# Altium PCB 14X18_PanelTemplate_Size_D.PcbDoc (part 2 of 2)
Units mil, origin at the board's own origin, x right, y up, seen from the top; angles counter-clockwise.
Board outline 18000 x 14000 mil, 2 copper layers (Top Layer, Bottom Layer); 52 components, 1 nets, 312 pads, 0 vias.
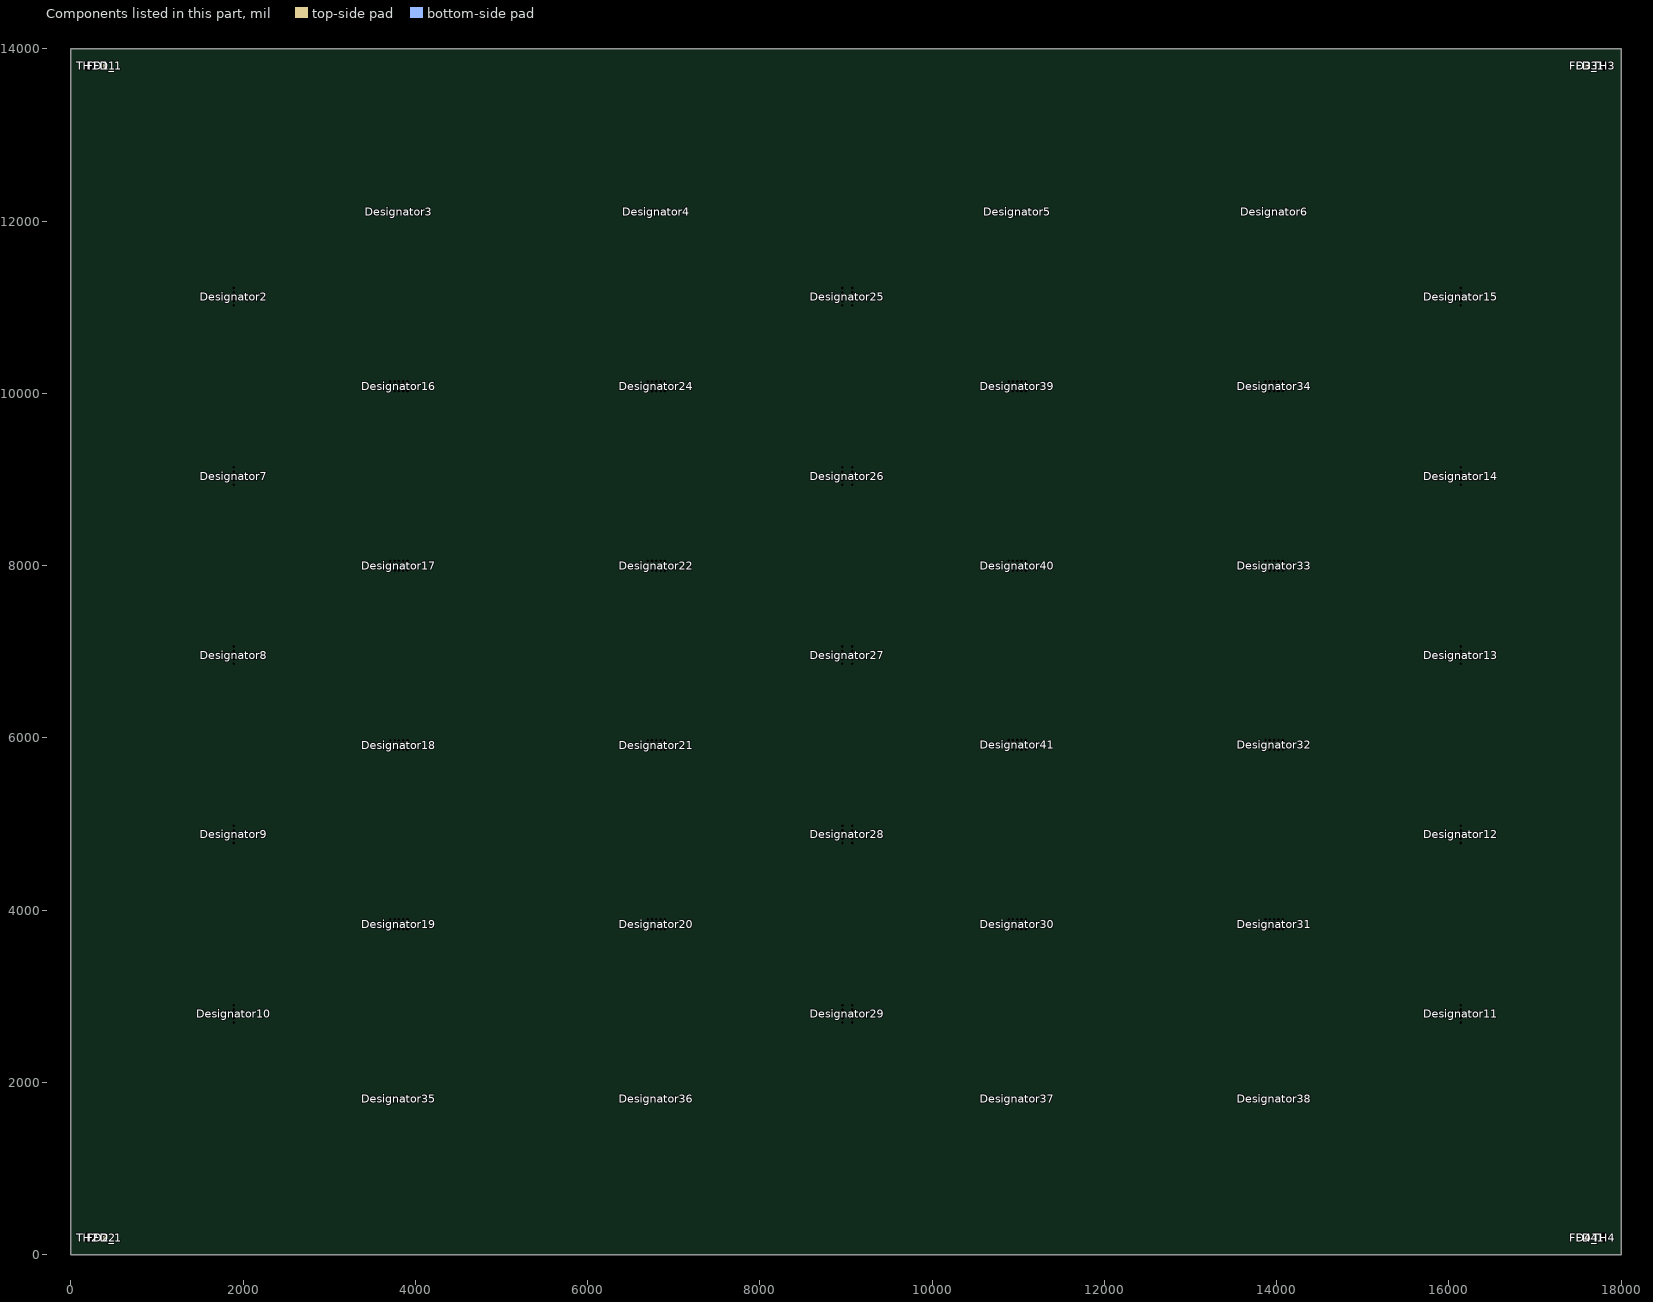
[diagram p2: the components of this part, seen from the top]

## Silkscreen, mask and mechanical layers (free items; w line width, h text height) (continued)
32_PANEL_CONTINUATION_BLOCK_MIRRORED:
  lines w1: -3000,-2999 31000,-2999 31000,19001 -3000,19001 -3000,-2999 ; -2700,-2699 -2700,18701 30700,18701 30700,-2699 -2700,-2699
  lines w5: -2849,2761 -2700,2761 ; -2700,-2550 405,-2550 ; -2700,-2235 405,-2235 405,-2550 ; -2700,-1500 -2700,-2700 1800,-2700 ; -2700,2651 -2849,2651 -2849,3761 -2700,3761 ; -2698,18046 1095,18046 1095,18696 ; -2698,18176 1095,18176 ; -2698,18306 1095,18306 ; -2698,18436 1095,18436 ; -2698,18566 1095,18566 ; -2400,-2550 -2400,-2235 ; -2105,18046 -2105,18566 ; -1940,-2700.1 -1940,-2550.1 ; -1505,18046 -1505,18566 ; -900,-2550 -900,-2235 ; -400,18701 -400,18850 710,18850 710,18701 ; -290,18701 -290,18850 ; -200,-2700 -200,-2550 ; 100,-2550 100,-2235 ; 405,-2700 405,-2550 ; 495,18046 495,18566 ; 795,18046 795,18566 ; 27823,-2699 27823,-2503 ; 27823,-2699 30700,-2699 ; 27823,-2699 30700,-2699 ; 27823,-2699 27823,-2503 ; 27823,-2699 30700,-2699 ; 27823,-2699 27823,-2503 ; 27823,-2503 30700,-2503 ; 27823,-2503 30700,-2503 ; 27823,-2503 30700,-2503 ; 30700,-2699 30700,-2503 ; 30700,-2699 30700,-2503 ; 30700,-2699 30700,-2503 ; 28640,18371 28640,18701 30700,18701 30700,18371 28640,18371
  lines w10: -3000,2651 -2700,2651 ; -3000,8001 -2700,8001 ; -3000,13351 -2700,13351 ; 5650,-2999 5650,-2699 ; 5650,18701 5650,19001 ; 14000,-2999 14000,-2699 ; 14000,18701 14000,19001 ; 22350,-2999 22350,-2699 ; 22350,18701 22350,19001 ; 30700,2651 31000,2651 ; 30700,8001 31000,8001 ; 30700,13351 31000,13351
  text "REV:" at -315.09,18816 h30
  text "DWG. NO." at 694.91,18816 h30
  text "4" at 1400,18776 h250
  text "3" at 9750,18776 h250
  text "2" at 18100,18776 h250
  text "1" at 26475,18776 h250
  text ".PCB_REV" at -330,18726 h50
  text ".PCB_DWG_NO" at 480,18726 h50
  text "R" at 28804.21,18628.61 h76
  text "O" at 28859.22,18628.61 h76
  text "N" at 28927.57,18628.61 h76
  text "I" at 28947.57,18628.61 h76
  text "E" at 28994.25,18628.61 h76
  text "R" at 29042.6,18628.61 h76
  text "E" at 29089.28,18628.61 h76
  text "H" at 29139.29,18628.61 h76
  text "D" at 29207.64,18628.61 h76
  text "E" at 29254.32,18628.61 h76
  text "S" at 29300.99,18628.61 h76
  text "O" at 29356.01,18628.61 h76
  text "L" at 29394.35,18628.61 h76
  text "C" at 29444.36,18628.61 h76
  text "S" at 29491.04,18628.61 h76
  text "I" at 29509.38,18628.61 h76
  text "D" at 29559.39,18628.61 h76
  text "A" at 29626.07,18628.61 h76
  text "T" at 29667.75,18628.61 h76
  text "A" at 29714.43,18628.61 h76
  text "D" at 29764.44,18628.61 h76
  text "E" at 29829.46,18628.61 h76
  text "H" at 29879.47,18628.61 h76
  text "T" at 29922.81,18628.61 h76
  text "D" at 29991.16,18628.61 h76
  text "N" at 30041.18,18628.61 h76
  text "A" at 30087.85,18628.61 h76
  text "T" at 30151.2,18628.61 h76
  text "N" at 30199.55,18628.61 h76
  text "E" at 30246.23,18628.61 h76
  text "M" at 30304.57,18628.61 h76
  text "U" at 30354.59,18628.61 h76
  text "C" at 30404.6,18628.61 h76
  text "O" at 30459.61,18628.61 h76
  text "D" at 30509.62,18628.61 h76
  text "S" at 30574.64,18628.61 h76
  text "I" at 30594.65,18628.61 h76
  text "H" at 30644.66,18628.61 h76
  text "T" at 30688,18628.61 h76
  text "REVISIONS" at -540,18596 h60
  text "Y" at 28700.15,18548.59 h76
  text "A" at 28745.16,18548.59 h76
  text "M" at 28803.5,18548.59 h76
  text "D" at 28873.52,18548.59 h76
  text "N" at 28923.53,18548.59 h76
  text "A" at 28970.21,18548.59 h76
  text "D" at 29038.56,18548.59 h76
  text "E" at 29085.24,18548.59 h76
  text "T" at 29128.58,18548.59 h76
  text "I" at 29148.59,18548.59 h76
  text "M" at 29205.27,18548.59 h76
  text "I" at 29225.27,18548.59 h76
  text "L" at 29263.62,18548.59 h76
  text "M" at 29340.3,18548.59 h76
  text "U" at 29390.32,18548.59 h76
  text "I" at 29410.32,18548.59 h76
  text "T" at 29453.66,18548.59 h76
  text "L" at 29490.34,18548.59 h76
  text "A" at 29537.02,18548.59 h76
  text "F" at 29600.37,18548.59 h76
  text "O" at 29653.71,18548.59 h76
  text "Y" at 29718.73,18548.59 h76
  text "T" at 29762.07,18548.59 h76
  text "R" at 29810.42,18548.59 h76
  text "E" at 29857.1,18548.59 h76
  text "P" at 29903.77,18548.59 h76
  text "O" at 29957.82,18548.59 h76
  text "R" at 30007.83,18548.59 h76
  text "P" at 30054.51,18548.59 h76
  text "E" at 30119.53,18548.59 h76
  text "H" at 30169.54,18548.59 h76
  text "T" at 30212.89,18548.59 h76
  text "S" at 30277.9,18548.59 h76
  text "I" at 30297.91,18548.59 h76
  text "H" at 30366.26,18548.59 h76
  text "T" at 30409.6,18548.59 h76
  text "I" at 30427.94,18548.59 h76
  text "W" at 30496.29,18548.59 h76
  text "E" at 30541.3,18548.59 h76
  text "R" at 30591.31,18548.59 h76
  text "E" at 30637.99,18548.59 h76
  text "H" at 30688,18548.59 h76
  text "DATE" at -1705,18471 h60
  text "REV" at 715,18471 h60
  text "ZONE" at 1045,18471 h60
  text "E" at 28919.92,18468.57 h76
  text "R" at 28969.94,18468.57 h76
  text "A" at 29016.61,18468.57 h76
  text "S" at 29081.63,18468.57 h76
  text "T" at 29124.97,18468.57 h76
  text "H" at 29173.32,18468.57 h76
  text "G" at 29228.33,18468.57 h76
  text "I" at 29248.34,18468.57 h76
  text "R" at 29296.68,18468.57 h76
  text "O" at 29371.7,18468.57 h76
  text "N" at 29421.71,18468.57 h76
  text "." at 29460.06,18468.57 h76
  text "E" at 29506.74,18468.57 h76
  text "L" at 29545.08,18468.57 h76
  text "O" at 29600.09,18468.57 h76
  text "H" at 29648.44,18468.57 h76
  text "W" at 29716.79,18468.57 h76
  text "N" at 29783.47,18468.57 h76
  text "I" at 29803.48,18468.57 h76
  text "D" at 29871.83,18468.57 h76
  text "E" at 29918.5,18468.57 h76
  text "T" at 29961.85,18468.57 h76
  text "U" at 30011.86,18468.57 h76
  text "B" at 30058.54,18468.57 h76
  text "I" at 30078.54,18468.57 h76
  text "R" at 30126.89,18468.57 h76
  text "T" at 30169.54,18468.57 h76
  text "S" at 30216.22,18468.57 h76
  text "I" at 30234.56,18468.57 h76
  text "D" at 30284.57,18468.57 h76
  text "Y" at 30351.25,18468.57 h76
  text "L" at 30389.6,18468.57 h76
  text "E" at 30436.27,18468.57 h76
  text "E" at 30481.28,18468.57 h76
  text "R" at 30531.3,18468.57 h76
  text "F" at 30574.64,18468.57 h76
  text "E" at 30641.32,18468.57 h76
  text "B" at 30688,18468.57 h76
  text "APPROVED" at -2210,18466 h60
  text "DESCRIPTION" at -300,18466 h60
  text "." at 28767.96,18388.55 h76
  text "N" at 28816.31,18388.55 h76
  text "E" at 28862.98,18388.55 h76
  text "V" at 28909.66,18388.55 h76
  text "I" at 28929.67,18388.55 h76
  text "G" at 28984.68,18388.55 h76
  text "E" at 29045.93,18388.55 h76
  text "E" at 29092.61,18388.55 h76
  text "T" at 29135.95,18388.55 h76
  text "N" at 29184.3,18388.55 h76
  text "A" at 29230.98,18388.55 h76
  text "R" at 29280.99,18388.55 h76
  text "A" at 29327.67,18388.55 h76
  text "W" at 29396.02,18388.55 h76
  text "D" at 29462.7,18388.55 h76
  text "E" at 29509.38,18388.55 h76
  text "I" at 29529.38,18388.55 h76
  text "L" at 29566.06,18388.55 h76
  text "P" at 29612.74,18388.55 h76
  text "M" at 29671.09,18388.55 h76
  text "I" at 29691.09,18388.55 h76
  text "R" at 29759.44,18388.55 h76
  text "O" at 29814.45,18388.55 h76
  text "S" at 29879.47,18388.55 h76
  text "S" at 29926.15,18388.55 h76
  text "E" at 29972.83,18388.55 h76
  text "R" at 30022.84,18388.55 h76
  text "P" at 30069.52,18388.55 h76
  text "X" at 30114.53,18388.55 h76
  text "E" at 30161.21,18388.55 h76
  text "R" at 30231.22,18388.55 h76
  text "O" at 30286.24,18388.55 h76
  text "D" at 30354.59,18388.55 h76
  text "E" at 30401.26,18388.55 h76
  text "V" at 30447.94,18388.55 h76
  text "R" at 30497.96,18388.55 h76
  text "E" at 30544.63,18388.55 h76
  text "S" at 30591.31,18388.55 h76
  text "E" at 30637.99,18388.55 h76
  text "R" at 30688,18388.55 h76
  text "ORIGINAL" at -375,18336 h60
  text "A" at 685,18336 h60
  text "A" at -2775,15901 h250
  text "A" at 30900,15901 h250
  text "B" at -2775,10551 h250
  text "B" at 30900,10551 h250
  text "C" at -2775,5201 h250
  text "C" at 30900,5201 h250
  text "DWG. NO." at -2815,3745.9 h30 r90
  text ".PCB_DWG_NO" at -2725,3531 h50 r90
  text "REV:" at -2815,2735.9 h30 r90
  text "D" at -2775,-149 h250
  text "D" at 30900,-149 h250
  text "REV:" at -2485,-2310 h45
  text "DWG NO:" at -925,-2310 h45
  text "CAGE CODE:" at 75,-2310 h45
  text "SIZE:" at 320,-2310 h45
  text ".PCB_DWG_NO" at -1235,-2450 h100
  text "B" at 280,-2455 h100
  text ".CAGE_CODE" at -95,-2465 h100
  text "SHEET:" at -1965,-2625.1 h45
  text "FILE NAME:" at -225,-2625.1 h45
  text "SCALE:" at 380,-2625 h45
  text ".Printout_Name" at 30644,-2646 h150
  text ".Printout_Name" at 30644,-2646 h150
  text ".Printout_Name" at 30644,-2646 h150
  text ".PCB_FILE_NAME_NO_PATH" at -568,-2670.1 h60
  text "OF" at -2415,-2675.1 h45
  text ".PCB_SCALE" at 110,-2675 h60
  text "DOC-104 REV A" at 30700,-2741.1 h20
  text "DOC-104 REV A" at 30700,-2741.1 h20
  text "DOC-104 REV A" at 30700,-2741.1 h20
  text "4" at 1400,-2924 h250
  text "3" at 9750,-2924 h250
  text "2" at 18100,-2924 h250
  text "1" at 26475,-2924 h250

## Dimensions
0,0 to 196.85,196.85 on 16_BOTTOM_COURTYARD
0,0 to 196.85,196.85 on 16_BOTTOM_COURTYARD

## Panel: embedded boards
"1SL1 Xilinx Spartan-11E PQ208.PcbDoc" at 1881.27,1800.22, 5 rows x 2 columns, spacing 2082.19 x 7180.61, rotation 0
